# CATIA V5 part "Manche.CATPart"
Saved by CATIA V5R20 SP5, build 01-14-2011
Part number: Manche
Publications: "Longueur_bielle"
Bounding box of the stored display mesh (mm): x -68 to 67.49, y 0 to 20, z -8 to 8
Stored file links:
  D:\Dropbox\IAO_2011\MMS_GR3\IAO_2011_1475_rguinot\IAO\IAO_2011_1475_rguinot\Manche.CATPart
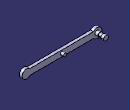
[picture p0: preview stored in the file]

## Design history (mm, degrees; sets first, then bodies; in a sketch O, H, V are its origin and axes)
Parameters
  Longueur_bielle = 60 mm
Body1 (main body)
  Sketch1 on zx-plane, origin (0, 0, 0), H (-1, 0, 0), V (0, 0, 1)
    arc A1 centre (60, 0) radius 8 from (53.755, -5) to (53.755, 5) ccw
    point P1 (60, 0)
    arc A2 centre (-60, 0) radius 7.5 from (-54.4098, 5) to (-54.4098, -5) ccw
    point P2 (-60, 0)
    line L1 (-54.4098, 5) -> (53.755, 5)
    line L2 (53.755, -5) -> (-54.4098, -5)
    reference intersected line E2 through (0, 0) direction (-1, 0) from xy-plane
    circle A3 centre (0, 0) radius 2.5
    distance P1 O = 60 {= Longueur_bielle}
    distance L1 L2 = 10
    radius A3 = 2.5
    distance O P2 = 60 {= Longueur_bielle}
    radius A2 = 7.5
    radius A1 = 8
    coincidence: P1 H, P2 H
    horizontal: L1 H, L2 H
    symmetry: L2 L1 E2
  MultiPad1: profile Sketch1, domains (length 5; length 10)
  Sketch2 on face of MultiPad1, origin (0, 5, 0), H (1, 0, 0), V (0, 0, 1)
    circle A1 centre (-60, 0) radius 3
    point P1 (-60, 0)
    circle A2 centre (-60, 0) radius 4
    distance P1 O = 60 {= Longueur_bielle}
    radius A1 = 3
    radius A2 = 4
    coincidence: P1 H
  MultiPad2: profile Sketch2, domains (length 5; length 15)
  Sketch3 on face of MultiPad2, origin (0, 20, 0), H (-1, 0, 0), V (0, 0, 1)
    circle A1 centre (60, 0) radius 4
    point P1 (60, 0)
    reference projected circle E1 centre (60, 0) radius 3 from edge [face of MultiPad2 | face of MultiPad2 from Sketch2.A1]
    radius A1 = 4
    coincidence: P1 H
    concentricity: P1 E1
  Pad1: profile Sketch3, direction (0, -1, 0), length 5
  Sketch4 on face of MultiPad1, origin (0, 5, 0), H (-1, 0, 0), V (0, 0, 1)
    point P1 (-60, 0)
    reference projected arc E1 centre (-60, 0) radius 7.5 from (-54.4098, 5) to (-54.4098, -5) ccw from edge [face of MultiPad1 from Sketch1.A2 | face of MultiPad1]
    concentricity: P1 E1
